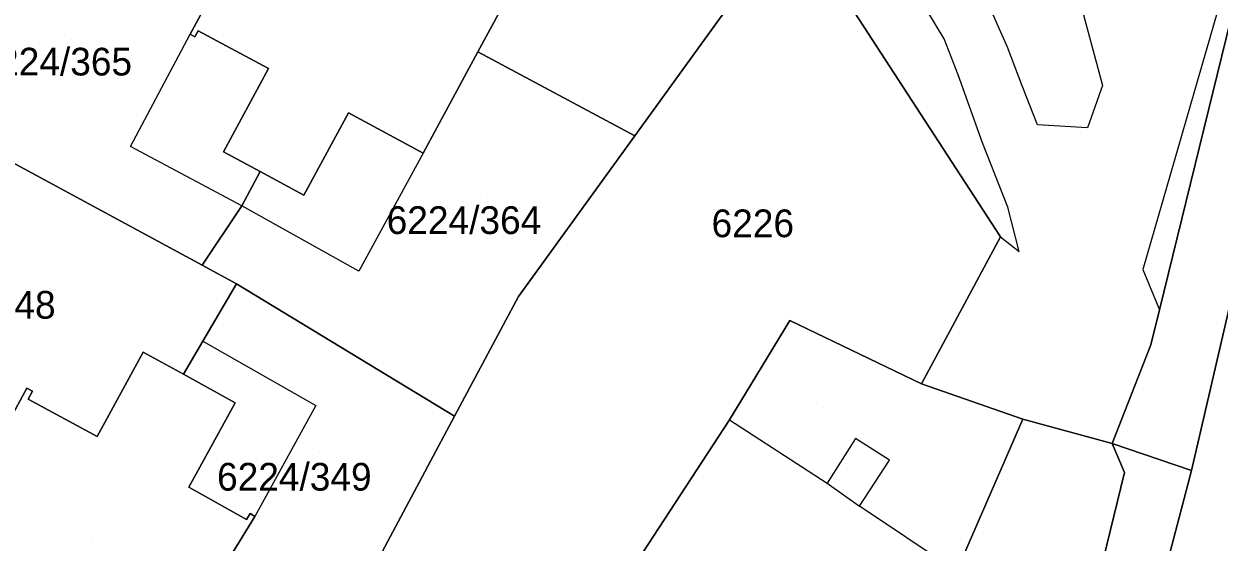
# Model space of a CAD drawing. Extents: x -266199 to -261993, y -1239047 to -1235108.
# Drawn here: x -263819.5 to -263733.3, y -1236276 to -1236238.6 of the extents above; entities that cross this region are included whole.
import ezdxf

# ---------------------------------------------------------------- set-up
doc = ezdxf.new("R2010")
doc.units = 0
for name, color, linetype in [('body_kn', 7, 'Continuous'), ('kladpar_druhypozemkov', 7, 'Continuous'), ('kladpar_hranice', 7, 'Continuous'), ('kladpar_parcelnecisla', 7, 'Continuous'), ('kladpar_plochy', 7, 'Continuous'), ('zappar_hrandruhpozemk', 7, 'Continuous')]:
    doc.layers.add(name, color=color, linetype=linetype)

msp = doc.modelspace()

# ---------------------------------------------------------------- linework, layer by layer
at = {"layer": 'body_kn'}
for p, q in [((-263807.5, -1236239.34), (-263807.5, -1236239.34)), ((-263806.91, -1236239.08), (-263806.91, -1236239.08)), ((-263807.15, -1236239.53), (-263807.15, -1236239.53)), ((-263753.1, -1236239.67), (-263753.1, -1236239.67)), ((-263748.52, -1236240.27), (-263748.52, -1236240.27)), ((-263786.73, -1236240.6), (-263786.73, -1236240.6)), ((-263801.85, -1236241.81), (-263801.85, -1236241.81)), ((-263752.08, -1236242.27), (-263752.08, -1236242.27)), ((-263747.47, -1236243.05), (-263747.47, -1236243.05)), ((-263741.66, -1236243.03), (-263741.66, -1236243.03)), ((-263796.08, -1236245), (-263796.08, -1236245)), ((-263746.36, -1236245.87), (-263746.36, -1236245.87)), ((-263742.75, -1236246.09), (-263742.75, -1236246.09)), ((-263775.41, -1236246.66), (-263775.41, -1236246.66)), ((-263750.33, -1236247.17), (-263750.33, -1236247.17)), ((-263811.8, -1236247.43), (-263811.8, -1236247.43)), ((-263805.09, -1236247.82), (-263805.09, -1236247.82)), ((-263790.68, -1236247.92), (-263790.68, -1236247.92)), ((-263790.68, -1236247.92), (-263790.68, -1236247.92)), ((-263802.45, -1236249.25), (-263802.45, -1236249.25)), ((-263799.29, -1236250.95), (-263799.29, -1236250.95)), ((-263803.77, -1236251.72), (-263803.77, -1236251.72)), ((-263803.77, -1236251.72), (-263803.77, -1236251.72)), ((-263748.49, -1236251.82), (-263748.49, -1236251.82)), ((-263749.03, -1236253.95), (-263749.03, -1236253.95)), ((-263749.03, -1236253.95), (-263749.03, -1236253.95)), ((-263747.68, -1236255.01), (-263747.68, -1236255.01)), ((-263806.64, -1236256), (-263806.64, -1236256)), ((-263806.64, -1236256), (-263806.64, -1236256)), ((-263795.32, -1236256.44), (-263795.32, -1236256.44)), ((-263738.76, -1236256.32), (-263738.76, -1236256.32)), ((-263804.15, -1236257.35), (-263804.15, -1236257.35)), ((-263783.8, -1236258.27), (-263783.8, -1236258.27)), ((-263737.73, -1236258.81), (-263737.73, -1236258.81)), ((-263737.55, -1236259.22), (-263737.55, -1236259.22)), ((-263764.22, -1236259.99), (-263764.22, -1236259.99)), ((-263764.22, -1236259.99), (-263764.22, -1236259.99)), ((-263806.58, -1236261.49), (-263806.58, -1236261.49)), ((-263806.58, -1236261.49), (-263806.58, -1236261.49)), ((-263738.17, -1236261.75), (-263738.17, -1236261.75)), ((-263810.89, -1236262.27), (-263810.89, -1236262.27)), ((-263807.98, -1236263.87), (-263807.98, -1236263.87)), ((-263819.28, -1236264.87), (-263819.28, -1236264.87)), ((-263818.87, -1236265.09), (-263818.87, -1236265.09)), ((-263754.73, -1236264.56), (-263754.73, -1236264.56)), ((-263819.18, -1236265.67), (-263819.18, -1236265.67)), ((-263804.25, -1236265.93), (-263804.25, -1236265.93)), ((-263798.43, -1236266.12), (-263798.43, -1236266.12)), ((-263788.43, -1236266.89), (-263788.43, -1236266.89)), ((-263768.57, -1236267.16), (-263768.57, -1236267.16)), ((-263768.57, -1236267.16), (-263768.57, -1236267.16)), ((-263747.42, -1236267.12), (-263747.42, -1236267.12)), ((-263814.21, -1236268.37), (-263814.21, -1236268.37)), ((-263759.48, -1236268.5), (-263759.48, -1236268.5)), ((-263740.96, -1236268.86), (-263740.96, -1236268.86)), ((-263740.96, -1236268.86), (-263740.96, -1236268.86)), ((-263757.04, -1236270.07), (-263757.04, -1236270.07)), ((-263740.08, -1236270.96), (-263740.08, -1236270.96)), ((-263735.23, -1236270.82), (-263735.23, -1236270.82)), ((-263735.23, -1236270.82), (-263735.23, -1236270.82)), ((-263807.6, -1236272.02), (-263807.6, -1236272.02)), ((-263761.53, -1236271.74), (-263761.53, -1236271.74)), ((-263761.53, -1236271.74), (-263761.53, -1236271.74)), ((-263803.17, -1236273.91), (-263803.17, -1236273.91)), ((-263759.2, -1236273.4), (-263759.2, -1236273.4)), ((-263759.2, -1236273.4), (-263759.2, -1236273.4)), ((-263803.44, -1236274.35), (-263803.44, -1236274.35)), ((-263802.82, -1236274.14), (-263802.82, -1236274.14))]:
    msp.add_line(p, q, dxfattribs=at)
at = {"layer": 'kladpar_druhypozemkov'}
for p, q in [((-263816.04, -1236239.71), (-263816.04, -1236239.71)), ((-263786.57, -1236251.15), (-263786.57, -1236251.15)), ((-263766.3, -1236251.38), (-263766.3, -1236251.38)), ((-263761.82, -1236266.28), (-263761.82, -1236266.28)), ((-263798.15, -1236269.45), (-263798.15, -1236269.45)), ((-263814.52, -1236275.64), (-263814.52, -1236275.64))]:
    msp.add_line(p, q, dxfattribs=at)
at = {"layer": 'kladpar_hranice'}
msp.add_line((-263735.23, -1236270.82), (-263740.96, -1236268.86), dxfattribs=at)
for points in [[(-263735.23, -1236270.82), (-263724.69, -1236225.29), (-263722.7, -1236216.71), (-263718.01, -1236196.46), (-263715.96, -1236194.69), (-263707.41, -1236187.32), (-263706.45, -1236187.77), (-263706.05, -1236188.26), (-263705.74, -1236188.65), (-263706.56, -1236199.39)], [(-263706.56, -1236199.39), (-263705.74, -1236188.65), (-263706.05, -1236188.26), (-263706.45, -1236187.77), (-263707.41, -1236187.32), (-263715.96, -1236194.69), (-263718.01, -1236196.46), (-263722.7, -1236216.71), (-263724.69, -1236225.29), (-263735.23, -1236270.82)], [(-263713.64, -1236188.23), (-263721.41, -1236193.43), (-263727.5, -1236218.27), (-263729.2, -1236225.19), (-263737.55, -1236259.22), (-263738.17, -1236261.75), (-263740.96, -1236268.86)], [(-263740.96, -1236268.86), (-263738.17, -1236261.75), (-263737.55, -1236259.22), (-263729.2, -1236225.19), (-263727.5, -1236218.27), (-263721.41, -1236193.43), (-263713.64, -1236188.23)], [(-263777, -1236216.79), (-263764.02, -1236230.89), (-263775.41, -1236246.66), (-263786.73, -1236240.6), (-263782.73, -1236233.19), (-263788.09, -1236230.14), (-263784.73, -1236224.22), (-263788.14, -1236222.29), (-263786.74, -1236219.75), (-263783.34, -1236213.57), (-263777, -1236216.79)], [(-263740.96, -1236268.86), (-263747.42, -1236267.12), (-263754.73, -1236264.56), (-263749.03, -1236253.95), (-263764.02, -1236230.89), (-263777, -1236216.79), (-263768.06, -1236221.44), (-263767.53, -1236222.81), (-263764.53, -1236225.69), (-263762.06, -1236227.85), (-263758.59, -1236231.94), (-263756.84, -1236233.93), (-263754.11, -1236228.7)], [(-263826.2, -1236245.42), (-263816.18, -1236226.75), (-263804.67, -1236232.36), (-263805.39, -1236233.73), (-263804.66, -1236234.09), (-263807.5, -1236239.34), (-263807.15, -1236239.53), (-263806.91, -1236239.08), (-263801.85, -1236241.81), (-263805.09, -1236247.82), (-263802.45, -1236249.25), (-263803.77, -1236251.72), (-263806.64, -1236256), (-263826.2, -1236245.42)], [(-263796.75, -1236282.5), (-263788.43, -1236266.89), (-263783.8, -1236258.27), (-263775.41, -1236246.66), (-263764.02, -1236230.89), (-263749.03, -1236253.95), (-263754.73, -1236264.56), (-263764.22, -1236259.99), (-263768.57, -1236267.16), (-263777.59, -1236280.96), (-263777.22, -1236281.21)], [(-263782.73, -1236233.19), (-263786.73, -1236240.6), (-263790.68, -1236247.92), (-263796.08, -1236245), (-263799.29, -1236250.95), (-263802.45, -1236249.25), (-263805.09, -1236247.82), (-263801.85, -1236241.81), (-263806.91, -1236239.08), (-263807.15, -1236239.53), (-263807.5, -1236239.34), (-263804.66, -1236234.09)], [(-263806.64, -1236256), (-263803.77, -1236251.72), (-263802.45, -1236249.25), (-263799.29, -1236250.95), (-263796.08, -1236245), (-263790.68, -1236247.92), (-263786.73, -1236240.6), (-263775.41, -1236246.66), (-263783.8, -1236258.27), (-263788.43, -1236266.89), (-263804.15, -1236257.35), (-263806.64, -1236256)], [(-263836.21, -1236264.06), (-263826.2, -1236245.42), (-263806.64, -1236256), (-263804.15, -1236257.35), (-263806.58, -1236261.49), (-263807.98, -1236263.87), (-263810.89, -1236262.27), (-263814.21, -1236268.37), (-263819.18, -1236265.67), (-263818.87, -1236265.09), (-263819.28, -1236264.87), (-263822.7, -1236271.16), (-263826.54, -1236269), (-263826.88, -1236269.78), (-263836.21, -1236264.06)], [(-263798.93, -1236286.46), (-263807.51, -1236281.78), (-263802.82, -1236274.14), (-263803.17, -1236273.91), (-263803.44, -1236274.35), (-263807.6, -1236272.02), (-263804.25, -1236265.93), (-263807.98, -1236263.87), (-263806.58, -1236261.49), (-263804.15, -1236257.35), (-263788.43, -1236266.89), (-263796.75, -1236282.5), (-263798.93, -1236286.46)], [(-263777.22, -1236281.21), (-263777.59, -1236280.96), (-263768.57, -1236267.16), (-263764.22, -1236259.99)], [(-263764.22, -1236259.99), (-263754.73, -1236264.56), (-263747.42, -1236267.12), (-263752.18, -1236278.07), (-263761.29, -1236291.85), (-263761.6, -1236291.64)], [(-263822.7, -1236271.16), (-263819.28, -1236264.87), (-263818.87, -1236265.09), (-263819.18, -1236265.67), (-263814.21, -1236268.37), (-263810.89, -1236262.27), (-263807.98, -1236263.87), (-263804.25, -1236265.93), (-263807.6, -1236272.02), (-263803.44, -1236274.35), (-263803.17, -1236273.91), (-263802.82, -1236274.14), (-263807.51, -1236281.78), (-263812.06, -1236289.19), (-263812.41, -1236289), (-263812.17, -1236288.56), (-263816.41, -1236286.25), (-263819.76, -1236292.38)], [(-263761.6, -1236291.64), (-263761.29, -1236291.85), (-263752.18, -1236278.07), (-263747.42, -1236267.12), (-263740.96, -1236268.86), (-263740.08, -1236270.96), (-263745.67, -1236293.91), (-263749.42, -1236308.46), (-263754.6, -1236309.83), (-263770.22, -1236299.9), (-263786.56, -1236289.23), (-263796.75, -1236282.5)], [(-263773.1, -1236380.05), (-263762.85, -1236355.68), (-263759.07, -1236345.06), (-263752.65, -1236320.75), (-263749.42, -1236308.46), (-263745.67, -1236293.91), (-263740.08, -1236270.96), (-263740.96, -1236268.86), (-263735.23, -1236270.82), (-263741.58, -1236295.05), (-263741.86, -1236296.2), (-263748.31, -1236321.94), (-263753.6, -1236341.79), (-263755.27, -1236347.57), (-263757.74, -1236355.23), (-263758.83, -1236357.94), (-263760.89, -1236363.24)], [(-263816.27, -1236490.31), (-263801.28, -1236456.18), (-263787.83, -1236425.05), (-263772.6, -1236390.11), (-263763.27, -1236368.54), (-263760.89, -1236363.24), (-263758.83, -1236357.94), (-263757.74, -1236355.23), (-263755.27, -1236347.57), (-263753.6, -1236341.79), (-263748.31, -1236321.94), (-263741.86, -1236296.2), (-263741.58, -1236295.05), (-263735.23, -1236270.82)]]:
    msp.add_lwpolyline(points, dxfattribs=at)
at = {"layer": 'kladpar_plochy'}
for p, q in [((-263735.23, -1236270.82), (-263724.69, -1236225.29)), ((-263741.58, -1236295.05), (-263735.23, -1236270.82))]:
    msp.add_line(p, q, dxfattribs=at)
for points in [[(-263777, -1236216.79), (-263764.02, -1236230.89), (-263775.41, -1236246.66), (-263786.73, -1236240.6), (-263782.73, -1236233.19), (-263788.09, -1236230.14), (-263784.73, -1236224.22), (-263788.14, -1236222.29), (-263786.74, -1236219.75), (-263783.34, -1236213.57)], [(-263782.73, -1236233.19), (-263786.73, -1236240.6), (-263790.68, -1236247.92), (-263796.08, -1236245), (-263799.29, -1236250.95), (-263802.45, -1236249.25), (-263805.09, -1236247.82), (-263801.85, -1236241.81), (-263806.91, -1236239.08), (-263807.15, -1236239.53), (-263807.5, -1236239.34), (-263804.66, -1236234.09), (-263805.39, -1236233.73), (-263804.67, -1236232.36), (-263803.89, -1236232.74), (-263803.24, -1236231.55), (-263798.87, -1236223.63), (-263798.52, -1236223.82), (-263798.79, -1236224.32), (-263793.77, -1236226.93), (-263790.48, -1236220.96), (-263788.14, -1236222.29), (-263784.73, -1236224.22), (-263788.09, -1236230.14)], [(-263826.2, -1236245.42), (-263816.18, -1236226.75), (-263804.67, -1236232.36), (-263805.39, -1236233.73), (-263804.66, -1236234.09), (-263807.5, -1236239.34), (-263807.15, -1236239.53), (-263806.91, -1236239.08), (-263801.85, -1236241.81), (-263805.09, -1236247.82), (-263802.45, -1236249.25), (-263803.77, -1236251.72), (-263806.64, -1236256)], [(-263806.64, -1236256), (-263803.77, -1236251.72), (-263802.45, -1236249.25), (-263799.29, -1236250.95), (-263796.08, -1236245), (-263790.68, -1236247.92), (-263786.73, -1236240.6), (-263775.41, -1236246.66), (-263783.8, -1236258.27), (-263788.43, -1236266.89), (-263804.15, -1236257.35)], [(-263836.21, -1236264.06), (-263826.2, -1236245.42), (-263806.64, -1236256), (-263804.15, -1236257.35), (-263806.58, -1236261.49), (-263807.98, -1236263.87), (-263810.89, -1236262.27), (-263814.21, -1236268.37), (-263819.18, -1236265.67), (-263818.87, -1236265.09), (-263819.28, -1236264.87), (-263822.7, -1236271.16), (-263826.54, -1236269), (-263826.88, -1236269.78)], [(-263798.93, -1236286.46), (-263807.51, -1236281.78), (-263802.82, -1236274.14), (-263803.17, -1236273.91), (-263803.44, -1236274.35), (-263807.6, -1236272.02), (-263804.25, -1236265.93), (-263807.98, -1236263.87), (-263806.58, -1236261.49), (-263804.15, -1236257.35), (-263788.43, -1236266.89), (-263796.75, -1236282.5)], [(-263764.22, -1236259.99), (-263754.73, -1236264.56), (-263747.42, -1236267.12), (-263752.18, -1236278.07), (-263761.29, -1236291.85), (-263761.6, -1236291.64), (-263766.13, -1236288.62), (-263766.51, -1236288.37), (-263765.69, -1236287.14), (-263771.49, -1236283.27), (-263772.3, -1236284.49), (-263772.68, -1236284.24), (-263777.22, -1236281.21), (-263777.59, -1236280.96), (-263768.57, -1236267.16)]]:
    msp.add_lwpolyline(points, close=True, dxfattribs=at)
for points in [[(-263729.2, -1236225.19), (-263737.55, -1236259.22), (-263738.17, -1236261.75), (-263740.96, -1236268.86), (-263747.42, -1236267.12), (-263754.73, -1236264.56), (-263749.03, -1236253.95), (-263764.02, -1236230.89)], [(-263724.69, -1236225.29), (-263735.23, -1236270.82), (-263740.96, -1236268.86), (-263738.17, -1236261.75), (-263737.55, -1236259.22), (-263729.2, -1236225.19)], [(-263796.75, -1236282.5), (-263788.43, -1236266.89), (-263783.8, -1236258.27), (-263775.41, -1236246.66), (-263764.02, -1236230.89), (-263749.03, -1236253.95), (-263754.73, -1236264.56), (-263764.22, -1236259.99), (-263768.57, -1236267.16), (-263777.59, -1236280.96)], [(-263822.7, -1236271.16), (-263819.28, -1236264.87), (-263818.87, -1236265.09), (-263819.18, -1236265.67), (-263814.21, -1236268.37), (-263810.89, -1236262.27), (-263807.98, -1236263.87), (-263804.25, -1236265.93), (-263807.6, -1236272.02), (-263803.44, -1236274.35), (-263803.17, -1236273.91), (-263802.82, -1236274.14), (-263807.51, -1236281.78), (-263812.06, -1236289.19), (-263812.41, -1236289), (-263812.17, -1236288.56), (-263816.41, -1236286.25), (-263819.76, -1236292.38)], [(-263752.18, -1236278.07), (-263747.42, -1236267.12), (-263740.96, -1236268.86), (-263740.08, -1236270.96), (-263745.67, -1236293.91)], [(-263773.1, -1236380.05), (-263762.85, -1236355.68), (-263759.07, -1236345.06), (-263752.65, -1236320.75), (-263749.42, -1236308.46), (-263745.67, -1236293.91), (-263740.08, -1236270.96), (-263740.96, -1236268.86), (-263735.23, -1236270.82), (-263741.58, -1236295.05), (-263741.86, -1236296.2), (-263748.31, -1236321.94), (-263753.6, -1236341.79), (-263755.27, -1236347.57), (-263757.74, -1236355.23), (-263758.83, -1236357.94), (-263760.89, -1236363.24)]]:
    msp.add_lwpolyline(points, dxfattribs=at)
at = {"layer": 'zappar_hrandruhpozemk'}
for p, q in [((-263729.74, -1236225.12), (-263738.76, -1236256.32)), ((-263743.44, -1236236.42), (-263741.66, -1236243.03)), ((-263750.33, -1236247.17), (-263752.08, -1236242.27)), ((-263741.66, -1236243.03), (-263742.75, -1236246.09)), ((-263768.57, -1236267.16), (-263761.53, -1236271.74)), ((-263759.48, -1236268.5), (-263761.53, -1236271.74)), ((-263757.04, -1236270.07), (-263759.48, -1236268.5)), ((-263759.2, -1236273.4), (-263757.04, -1236270.07)), ((-263761.53, -1236271.74), (-263759.2, -1236273.4)), ((-263752.18, -1236278.07), (-263759.2, -1236273.4))]:
    msp.add_line(p, q, dxfattribs=at)
for points in [[(-263742.75, -1236246.09), (-263746.36, -1236245.87), (-263747.47, -1236243.05), (-263748.52, -1236240.27), (-263749.95, -1236237.07), (-263751.49, -1236233.27), (-263749.21, -1236233.94)], [(-263752.08, -1236242.27), (-263753.1, -1236239.67), (-263754.35, -1236237.6), (-263756.07, -1236234.81), (-263756.84, -1236233.93)], [(-263803.77, -1236251.72), (-263811.8, -1236247.43), (-263807.5, -1236239.34)], [(-263749.03, -1236253.95), (-263747.68, -1236255.01), (-263748.49, -1236251.82), (-263750.33, -1236247.17)], [(-263790.68, -1236247.92), (-263795.32, -1236256.44), (-263803.77, -1236251.72)], [(-263738.76, -1236256.32), (-263737.73, -1236258.81), (-263737.55, -1236259.22)], [(-263806.58, -1236261.49), (-263798.43, -1236266.12), (-263802.82, -1236274.14)]]:
    msp.add_lwpolyline(points, dxfattribs=at)

# ---------------------------------------------------------------- texts
at = {"layer": 'kladpar_parcelnecisla'}
for s, p in [('6224/365', (-263822.843, -1236242.31)), ('6224/364', (-263793.317, -1236253.75)), ('6226', (-263769.873, -1236253.98)), ('6224/348', (-263828.361, -1236259.86)), ('6224/349', (-263805.557, -1236272.27))]:
    msp.add_text(s, height=2, dxfattribs=at).set_placement(p)

doc.saveas('drawing.dxf')
